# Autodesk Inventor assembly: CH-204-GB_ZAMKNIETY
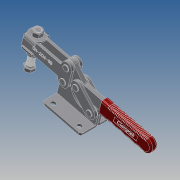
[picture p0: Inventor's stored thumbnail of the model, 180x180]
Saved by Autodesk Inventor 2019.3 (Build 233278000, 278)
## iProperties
Company: ·L?¤¤?
Created: 2010-06
Part Number: CH-204-GB_ZAMKNIETY
Material: Ogólny
Description: STEP AP203
Document SubType Name: Assembly
Designer: CADENGINEERING4
Sending System: SolidWorks 2005179
Preprocessor: SwSTEP 2.0
Title: CH-204-GB.STEP
Author: ·L?¥Î?
Revision Number: ANY
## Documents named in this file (12)
- E:\STRONA\Horizontal toggle clamp\CH-204-GB\CH-204-GB_ZAMKNIETY.iam
- E:\STRONA\Horizontal toggle clamp\CH-204-GB\204-GB-06___.ipt
- E:\STRONA\Horizontal toggle clamp\CH-204-GB\CH-FC-12300-01___.ipt
- E:\STRONA\Horizontal toggle clamp\CH-204-GB\204-GB-05___.ipt
- E:\STRONA\Horizontal toggle clamp\CH-204-GB\204-GB-01___.ipt
- E:\STRONA\Horizontal toggle clamp\CH-204-GB\204-GB-08___.ipt
- E:\STRONA\Horizontal toggle clamp\CH-204-GB\FW120(2)___.ipt
- E:\STRONA\Horizontal toggle clamp\CH-204-GB\204-GB-04___.ipt
- E:\STRONA\Horizontal toggle clamp\CH-204-GB\204-GB-02___.ipt
- E:\STRONA\Horizontal toggle clamp\CH-204-GB\204-GB-07___.ipt
- E:\STRONA\Horizontal toggle clamp\CH-204-GB\204-GB-03___.ipt
- E:\STRONA\Horizontal toggle clamp\CH-204-GB\CH-FC-12130___.ipt
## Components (23 placed, 23 different names)
1. 204-GB-06_??_1 — Zestawiające:30, Zestawiające:32
2. CH-FC-12300-01_??_2 — Równoległe:3, Zestawiające:3, Zestawiające:4
3. 204-GB-05_??_3 — Zestawiające:39, Zestawiające:41
4. 204-GB-01_??_4 — Zestawiające:19, Zestawiające:20, Zestawiające:21, Zestawiające:22, Zestawiające:23, Zestawiające:38, Zestawiające:39, Zestawiające:40, Zestawiające:41, Zestawiające:43, Przejściowe:1
5. 204-GB-08_??_5 — Zestawiające:17, Zestawiające:18, Zestawiające:47
6. FW120(2)_??_6 — Równoległe:2, Zestawiające:2, Zestawiające:6, Zestawiające:7
7. 204-GB-05_??_7 — Zestawiające:20, Zestawiające:21, Zestawiające:24
8. 204-GB-06_??_8 — Zestawiające:13, Zestawiające:16
9. 204-GB-04_??_9 — Zestawiające:27, Zestawiające:28, Zestawiające:29, Zestawiające:30, Zestawiające:32
10. FW120(2)_??_10 — Równoległe:1, Równoległe:2, Zestawiające:1, Zestawiające:4, Zestawiające:8
11. 204-GB-06_??_11 — Zestawiające:14, Zestawiające:15, Zestawiające:46
12. 204-GB-05_??_12 — Zestawiające:19, Zestawiające:22, Zestawiające:27
13. 204-GB-08_??_13 — Zestawiające:23, Zestawiające:25, Zestawiające:26, Zestawiające:28
14. 204-GB-02_??_14 — Równoległe:1, Zestawiające:7, Zestawiające:8, Zestawiające:9, Zestawiające:13, Zestawiające:14, Zestawiające:15, Zestawiające:16, Zestawiające:17, Zestawiające:18, Zestawiające:42, Zestawiające:43, Zestawiające:44, Zestawiające:45
15. 204-GB-06_??_15 — Zestawiające:31, Zestawiające:33, Zestawiające:36
16. 204-GB-08_??_16 — Zestawiające:44, Zestawiające:45
17. 204-GB-07_??_17 — Zestawiające:10, Zestawiające:11, Zestawiające:12
18. 204-GB-03_??_18 — Zestawiające:10, Zestawiające:11, Zestawiające:12, Zestawiające:36, Zestawiające:37, Zestawiające:46, Zestawiające:47, Przejściowe:1
19. 204-GB-08_??_19 — Zestawiające:34, Zestawiające:35, Zestawiające:37
20. 204-GB-05_??_20 — Zestawiające:38, Zestawiające:40, Zestawiające:42
21. CH-FC-12130_??_21 — Równoległe:3, Zestawiające:1, Zestawiające:2, Zestawiające:3, Zestawiające:5, Zestawiające:9
22. CH-FC-12300-01_??_22 — Zestawiające:5, Zestawiające:6
23. 204-GB-04_??_23 — Zestawiające:24, Zestawiające:25, Zestawiające:26, Zestawiające:29, Zestawiające:31, Zestawiające:33, Zestawiające:34, Zestawiające:35
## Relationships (51: Mate 47, Flush 3, Transitional 1)
- Równoległe:1 [Flush]: FW120(2)_??_10 ↔ 204-GB-02_??_14
- Równoległe:2 [Flush]: FW120(2)_??_6 ↔ FW120(2)_??_10
- Równoległe:3 [Flush]: CH-FC-12300-01_??_2 ↔ CH-FC-12130_??_21
- Zestawiające:1 [Mate]: FW120(2)_??_10 ↔ CH-FC-12130_??_21
- Zestawiające:2 [Mate]: FW120(2)_??_6 ↔ CH-FC-12130_??_21
- Zestawiające:3 [Mate]: CH-FC-12300-01_??_2 ↔ CH-FC-12130_??_21
- Zestawiające:4 [Mate]: CH-FC-12300-01_??_2 ↔ FW120(2)_??_10
- Zestawiające:5 [Mate]: CH-FC-12130_??_21 ↔ CH-FC-12300-01_??_22
- Zestawiające:6 [Mate]: FW120(2)_??_6 ↔ CH-FC-12300-01_??_22
- Zestawiające:7 [Mate]: FW120(2)_??_6 ↔ 204-GB-02_??_14
- Zestawiające:8 [Mate]: FW120(2)_??_10 ↔ 204-GB-02_??_14
- Zestawiające:9 [Mate]: 204-GB-02_??_14 ↔ CH-FC-12130_??_21
- Zestawiające:10 [Mate]: 204-GB-07_??_17 ↔ 204-GB-03_??_18
- Zestawiające:11 [Mate]: 204-GB-07_??_17 ↔ 204-GB-03_??_18
- Zestawiające:12 [Mate]: 204-GB-07_??_17 ↔ 204-GB-03_??_18
- Zestawiające:13 [Mate]: 204-GB-06_??_8 ↔ 204-GB-02_??_14
- Zestawiające:14 [Mate]: 204-GB-06_??_11 ↔ 204-GB-02_??_14
- Zestawiające:15 [Mate]: 204-GB-06_??_11 ↔ 204-GB-02_??_14
- Zestawiające:16 [Mate]: 204-GB-06_??_8 ↔ 204-GB-02_??_14
- Zestawiające:17 [Mate]: 204-GB-08_??_5 ↔ 204-GB-02_??_14
- Zestawiające:18 [Mate]: 204-GB-08_??_5 ↔ 204-GB-02_??_14
- Zestawiające:19 [Mate]: 204-GB-01_??_4 ↔ 204-GB-05_??_12
- Zestawiające:20 [Mate]: 204-GB-01_??_4 ↔ 204-GB-05_??_7
- Zestawiające:21 [Mate]: 204-GB-01_??_4 ↔ 204-GB-05_??_7
- Zestawiające:22 [Mate]: 204-GB-01_??_4 ↔ 204-GB-05_??_12
- Zestawiające:23 [Mate]: 204-GB-01_??_4 ↔ 204-GB-08_??_13
- Zestawiające:24 [Mate]: 204-GB-05_??_7 ↔ 204-GB-04_??_23
- Zestawiające:25 [Mate]: 204-GB-08_??_13 ↔ 204-GB-04_??_23
- Zestawiające:26 [Mate]: 204-GB-08_??_13 ↔ 204-GB-04_??_23
- Zestawiające:27 [Mate]: 204-GB-04_??_9 ↔ 204-GB-05_??_12
- Zestawiające:28 [Mate]: 204-GB-04_??_9 ↔ 204-GB-08_??_13
- Zestawiające:29 [Mate]: 204-GB-04_??_9 ↔ 204-GB-04_??_23
- Zestawiające:30 [Mate]: 204-GB-06_??_1 ↔ 204-GB-04_??_9
- Zestawiające:31 [Mate]: 204-GB-06_??_15 ↔ 204-GB-04_??_23
- Zestawiające:32 [Mate]: 204-GB-06_??_1 ↔ 204-GB-04_??_9
- Zestawiające:33 [Mate]: 204-GB-06_??_15 ↔ 204-GB-04_??_23
- Zestawiające:34 [Mate]: 204-GB-08_??_19 ↔ 204-GB-04_??_23
- Zestawiające:35 [Mate]: 204-GB-08_??_19 ↔ 204-GB-04_??_23
- Zestawiające:36 [Mate]: 204-GB-06_??_15 ↔ 204-GB-03_??_18
- Zestawiające:37 [Mate]: 204-GB-03_??_18 ↔ 204-GB-08_??_19
- Zestawiające:38 [Mate]: 204-GB-01_??_4 ↔ 204-GB-05_??_20
- Zestawiające:39 [Mate]: 204-GB-05_??_3 ↔ 204-GB-01_??_4
- Zestawiające:40 [Mate]: 204-GB-01_??_4 ↔ 204-GB-05_??_20
- Zestawiające:41 [Mate]: 204-GB-05_??_3 ↔ 204-GB-01_??_4
- Zestawiające:42 [Mate]: 204-GB-02_??_14 ↔ 204-GB-05_??_20
- Zestawiające:43 [Mate]: 204-GB-01_??_4 ↔ 204-GB-02_??_14
- Zestawiające:44 [Mate]: 204-GB-02_??_14 ↔ 204-GB-08_??_16
- Zestawiające:45 [Mate]: 204-GB-02_??_14 ↔ 204-GB-08_??_16
- Zestawiające:46 [Mate]: 204-GB-06_??_11 ↔ 204-GB-03_??_18
- Zestawiające:47 [Mate]: 204-GB-08_??_5 ↔ 204-GB-03_??_18
- Przejściowe:1 [Transitional]: 204-GB-01_??_4 ↔ 204-GB-03_??_18
